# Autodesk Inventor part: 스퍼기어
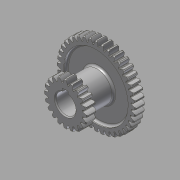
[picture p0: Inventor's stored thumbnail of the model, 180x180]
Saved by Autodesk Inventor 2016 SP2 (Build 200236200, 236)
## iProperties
Created: 2015-09
Part Number: 스퍼기어
Material: 강철, 연강
Document SubType Name: Modeling
Designer: mduedu
Density: 7.86 g/cm^3
Mass: 345.726 g
Surface Area: 225.641 cm^2
Volume: 43.9855 cm^3
Appearance: 강철
Author: mduedu
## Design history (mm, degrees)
sketch "스케치1"
  geometry: C1 r 38 at (0, 0); C2 r 40 at (0, 0); C3 r 35.5 at (0, 0); 1 further point
  constraints: 3 centre point, 3 coincident
  dimensions: "d0" = 76 diameter of C1; "d2" = 2 radial gap between concentric circles of C2 C1; "d3" = 71 diameter of C3 (computed from d0)
extrude "돌출1" new body sketch "스케치1" stored distance "d4" = 10; taper "d5" = 0 deg
sketch "스케치2"
  geometry: L1 (0, 35.5)-(0, -35.5); L2 (0, 0)-(40, 0); L3 (0, 0.57)-(39.996, 0.57); L4 (0, 1.57)-(39.969, 1.57); L5 (0, 2.07)-(39.946, 2.07); A1 r 35.5 centre (0, 0) between (0, 35.5) and (0, -35.5) reference; A2 r 40 centre (0, 0) between (40, 0) and (39.946, 2.07) reference; A3 r 9.234 centre (34.93, -7.149) between (39.996, 0.57) and (35.44, 2.07); A4 r 9.234 centre (34.93, 7.149) between (35.44, -2.07) and (39.996, -0.57); A5 r 40 centre (0, 0) between (39.996, -0.57) and (39.996, 0.57); A6 r 35.5 centre (0, 0) between (35.44, -2.07) and (35.44, 2.07); 4 further points
  constraints: 16 point on circle, 10 end point, 6 point on line, 4 centre point, 3 coincident, 3 parallel, 3 symmetric about line, 2 midpoint, 1 perpendicular, 1 vertical, 3 other
  dimensions: "d6" = 0.5 distance between parallel lines of L4 L5; "d8" = 1 distance between parallel lines of L3 L4; "d9" = 1.57 distance between parallel lines of L2 L4
extrude "돌출2" join sketch "스케치2" distance "d10" = 5; taper "d12" = 0 deg; dims "d11" = 5, "d13" = 0
fillet "모깎기1" dims "d17" = 0.5
chamfer "모따기1" distance "d21" = 1; stored, may be unused: second distance "d22" = 2, angle "d23" = 45 deg
sketch "스케치3"
  geometry: C1 r 32.5 at (0, 0); C2 r 15 at (0, 0); 1 further point
  constraints: 2 centre point, 2 coincident
  dimensions: "d27" = 65 diameter of C1; "d28" = 30 diameter of C2
extrude "돌출3" cut sketch "스케치3" distance "d29" = 3; taper "d30" = 0 deg
fillet "모깎기2" dims "d31" = 2
node "작업 평면2"
  node "작업 평면1"
sketch "스케치4"
  geometry: C1 r 15 at (0, 0) reference; 1 further point
extrude "돌출4" join sketch "스케치4" stored distance "d34" = 3; taper "d35" = 0 deg
sketch "스케치5"
  geometry: C1 r 17.5 at (0, 0); C2 r 20 at (0, 0); C3 r 22 at (0, 0); 1 further point
  constraints: 3 centre point, 3 coincident
  dimensions: "d36" = 40 diameter of C2; "d38" = 2 radial gap between concentric circles of C2 C3; "d39" = 35 diameter of C1 (= d36 - 2.5 x d38)
extrude "돌출6" join sketch "스케치5" distance "d46" = 10; taper "d47" = 0 deg
sketch "스케치6"
  geometry: L1 (0, 0)-(0, 22); L2 (-17.5, 0)-(17.5, 0); L3 (-0.57, 0)-(-0.57, 21.993); L4 (-1.57, 0)-(-1.57, 21.944); L5 (-2.07, 0)-(-2.07, 21.902); A1 r 22 centre (0, 0) between (0, 22) and (-0.57, 21.993) reference; A2 r 17.5 centre (0, 0) between (-17.5, 0) and (17.5, 0) reference; A3 r 9.431 centre (7.348, 16.868) between (-0.57, 21.993) and (-2.07, 17.377); A4 r 9.431 centre (-7.348, 16.868) between (2.07, 17.377) and (0.57, 21.993); A5 r 17.5 centre (0, 0) between (2.07, 17.377) and (-2.07, 17.377); A6 r 22 centre (0, 0) between (0.57, 21.993) and (-0.57, 21.993); 4 further points
  constraints: 16 point on circle, 10 end point, 5 point on line, 4 centre point, 3 coincident, 3 symmetric about line, 2 parallel, 2 perpendicular, 1 midpoint, 1 vertical, 3 other
  dimensions: "d40" = 0.5 distance between parallel lines of L4 L5; "d42" = 1 distance between parallel lines of L3 L4; "d43" = 1.57 distance between parallel lines of L1 L4
extrude "돌출5" join sketch "스케치6" distance "d44" = 10; taper "d45" = 0 deg
fillet "모깎기3" dims "d48" = 0.5
chamfer "모따기2" distance "d49" = 1; stored, may be unused: second distance "d50" = 2, angle "d51" = 45 deg
sketch "스케치7"
  geometry: C1 r 10 at (0, 0); 1 further point
  constraints: 1 centre point, 1 coincident
  dimensions: "d55" = 20 diameter of C1
extrude "돌출7" cut sketch "스케치7" stored distance "d56" = 10; taper "d57" = 0 deg
sketch "스케치8"
  geometry: L1 (-9.539, -3)-(-12.8, -3); L2 (-12.8, -3)-(-12.8, 3); L3 (-12.8, 3)-(-9.539, 3); L4 (-9.539, 3)-(-9.539, -3); A1 r 10 centre (0, 0) between (-9.539, -3) and (-9.539, 3) reference; 2 further points
  constraints: 8 end point, 3 point on circle, 2 parallel, 1 horizontal, 1 horizontal alignment, 1 perpendicular
  dimensions: "d58" = 6 distance of L1.end L2.end; "d60" = 22.8 distance from line of point (10, 0) L2
extrude "돌출8" cut sketch "스케치8" stored distance "d61" = 10; taper "d62" = 0 deg
chamfer "모따기3" distance "d63" = 1; stored, may be unused: second distance "d64" = 2, angle "d65" = 45 deg
fillet "모깎기4" dims "d66" = 2
node "솔리드1"
pattern_circular "원형 패턴3" dims "d25" = 360 deg
mirror "대칭1"
pattern_circular "원형 패턴4" dims "d53" = 360 deg
other parameters: "d32" = 9
